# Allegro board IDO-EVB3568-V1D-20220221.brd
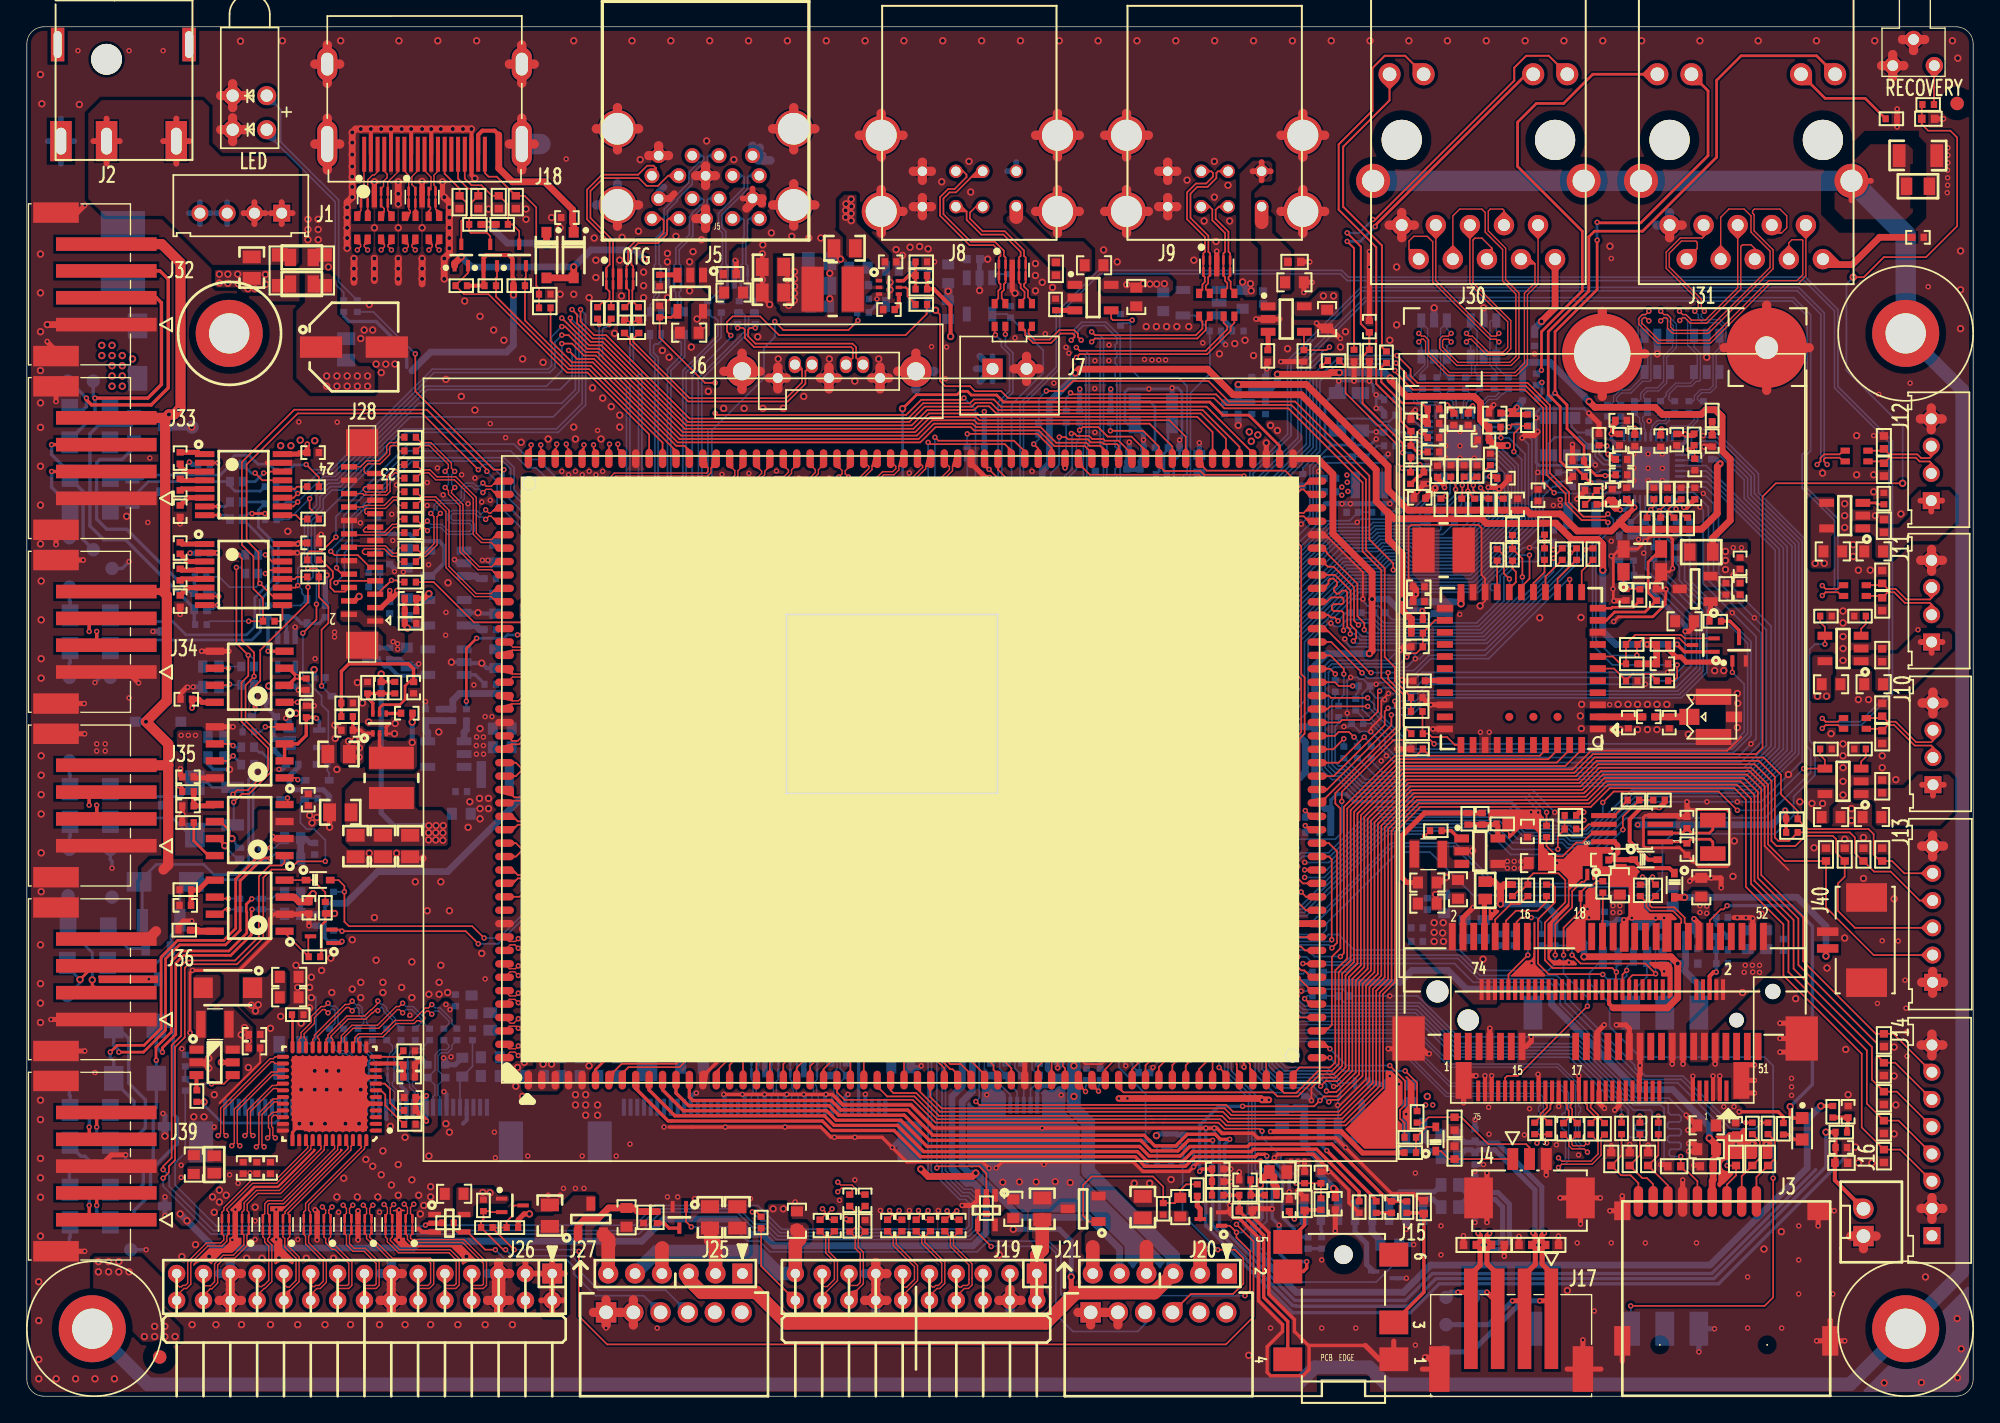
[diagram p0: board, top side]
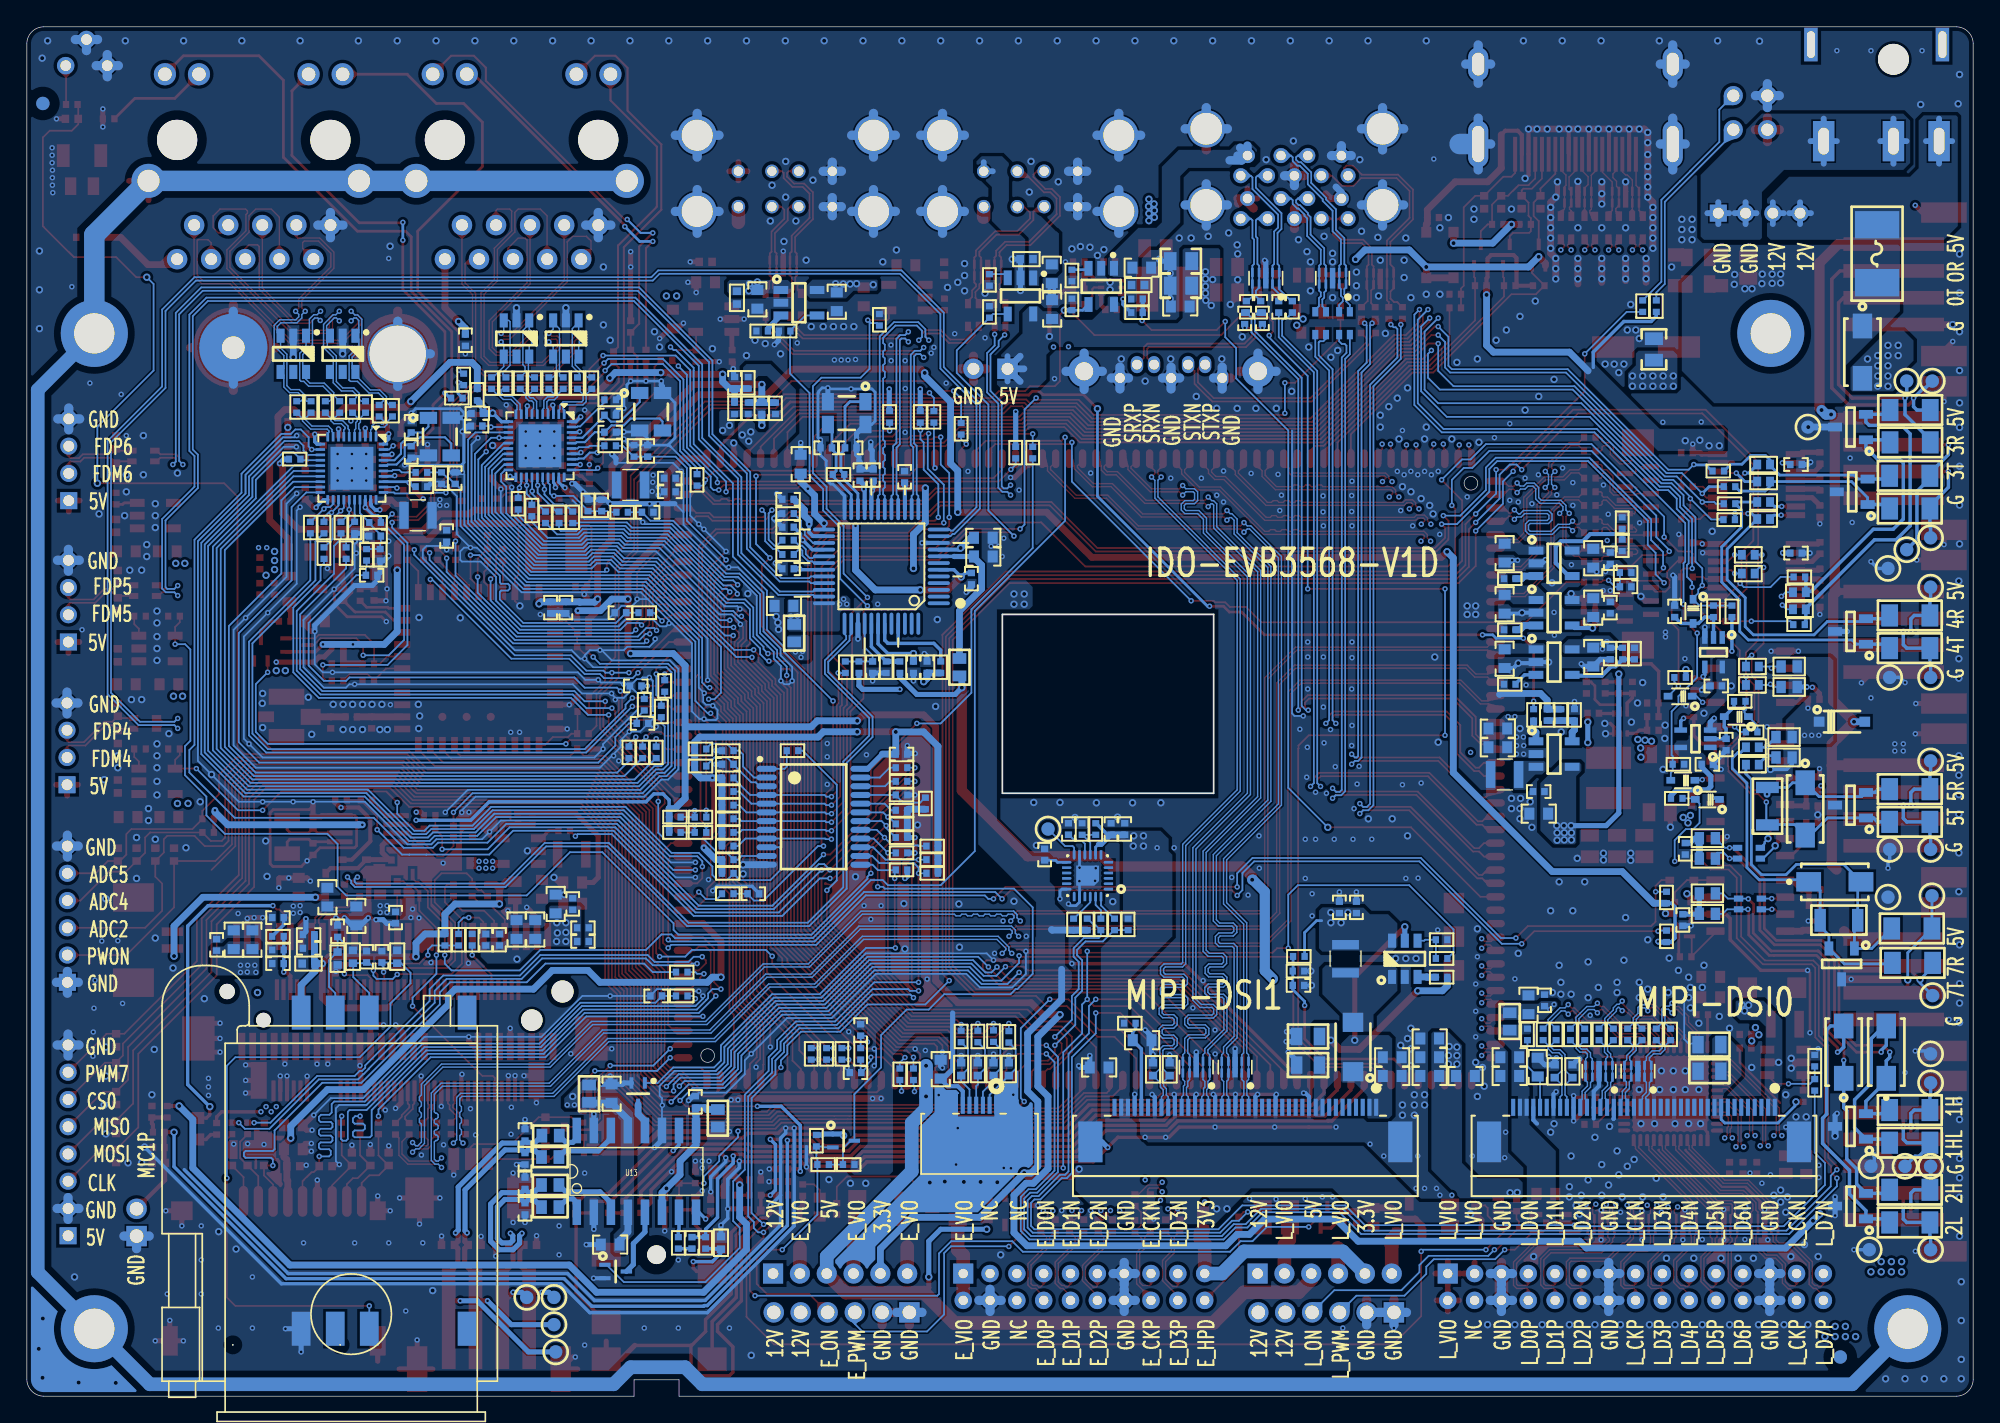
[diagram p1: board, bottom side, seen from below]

Outline 145.08 x 102.11 mm; copper layers: TOP, VCC, GND, BOTTOM. Coordinates in mm from the lower left corner of the outline.
Outline path: 0,100.84 arc(0.37,101.74) 1.27,102.11 143.81,102.11 arc(144.71,101.74) 145.08,100.84 145.08,1.27 arc(144.71,0.37) 143.81,0 99.82,0 99.82,1.22 96.47,1.22 96.47,0 1.27,0 arc(0.37,0.37) 0,1.27 0,100.84

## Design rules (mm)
net group DIFFPAIR0: nets HDMI_TX_D2N HDMI_TX_D2P
net group DIFFPAIR1: nets HDMI_TX_D2N_ HDMI_TX_D2P_
net group DIFFPAIR2: nets HDMI_TX_D1N_ HDMI_TX_D1P_
net group DIFFPAIR3: nets HDMI_TX_D1N HDMI_TX_D1P
net group DIFFPAIR4: nets HDMI_TX_D0N_ HDMI_TX_D0P_
net group DIFFPAIR5: nets HDMI_TX_D0N HDMI_TX_D0P
net group DIFFPAIR6: nets HDMI_TX_CLKN_ HDMI_TX_CLKP_
net group DIFFPAIR7: nets HDMI_TX_CLKN HDMI_TX_CLKP
net group DIFFPAIR8: nets USB2_HOST3_DM_ USB2_HOST3_DP_
net group DIFFPAIR9: nets FE2.1_DM1_ FE2.1_DP1_
net group DIFFPAIR10: nets FE2.1_DM1 FE2.1_DP1
net group DIFFPAIR11: nets USB2_HOST3_DM USB2_HOST3_DP
net group DIFFPAIR12: nets FE2.1_DM2_ FE2.1_DP2_
net group DIFFPAIR13: nets FE2.1_DM3_ FE2.1_DP3_
net group DIFFPAIR14: nets FE2.1_DM2 FE2.1_DP2
net group DIFFPAIR15: nets FE2.1_DM3 FE2.1_DP3
net group DIFFPAIR16: nets LVDS0_D0N LVDS0_D0P
net group DIFFPAIR17: nets LVDS0_D1N LVDS0_D1P
net group DIFFPAIR18: nets LVDS0_D2N LVDS0_D2P
net group DIFFPAIR19: nets LVDS0_CLKN LVDS0_CLKP
net group DIFFPAIR20: nets LVDS0_D3N LVDS0_D3P
net group DIFFPAIR21: nets LVDS1_D0N LVDS1_D0P
net group DIFFPAIR22: nets LVDS1_D1N LVDS1_D1P
net group DIFFPAIR23: nets LVDS1_D2N LVDS1_D2P
net group DIFFPAIR24: nets LVDS1_CLKN LVDS1_CLKP
net group DIFFPAIR25: nets LVDS1_D3N LVDS1_D3P
net group DIFFPAIR26: nets EDP_TX_D3N EDP_TX_D3P
net group DIFFPAIR27: nets EDP_TX_D3N_ EDP_TX_D3P_
net group DIFFPAIR28: nets EDP_TX_AUXN EDP_TX_AUXP
net group DIFFPAIR29: nets EDP_TX_AUXN_ EDP_TX_AUXP_
net group DIFFPAIR30: nets EDP_TX_D2N EDP_TX_D2P
net group DIFFPAIR31: nets EDP_TX_D2N_ EDP_TX_D2P_
net group DIFFPAIR32: nets EDP_TX_D1N EDP_TX_D1P
net group DIFFPAIR33: nets EDP_TX_D1N_ EDP_TX_D1P_
net group DIFFPAIR34: nets EDP_TX_D0N EDP_TX_D0P
net group DIFFPAIR35: nets EDP_TX_D0N_ EDP_TX_D0P_
net group DIFFPAIR36: nets USB3_HOST1_SSRXN_ USB3_HOST1_SSRXP_
net group DIFFPAIR37: nets USB3_HOST1_DM_ USB3_HOST1_DP_
net group DIFFPAIR38: nets USB3_OTG0_DM_ USB3_OTG0_DP_
net group DIFFPAIR39: nets USB3_OTG0_SSTXN_ USB3_OTG0_SSTXP_
net group DIFFPAIR40: nets USB3_HOST1_SSTXN_ USB3_HOST1_SSTXP_
net group DIFFPAIR41: nets USB3_HOST1_SSTXN USB3_HOST1_SSTXP
net group DIFFPAIR42: nets SATA1_TXN SATA1_TXP
net group DIFFPAIR43: nets USB3_OTG0_SSTXN USB3_OTG0_SSTXP
net group DIFFPAIR44: nets USB3_OTG0_DM USB3_OTG0_DP
net group DIFFPAIR45: nets USB3_HOST1_DM USB3_HOST1_DP
net group DIFFPAIR46: nets SATA1_RXN SATA1_RXP
net group DIFFPAIR47: nets USB3_HOST1_SSRXN USB3_HOST1_SSRXP
net group DIFFPAIR48: nets USB3_OTG0_SSRXN_ USB3_OTG0_SSRXP_
net group DIFFPAIR49: nets USB3_OTG0_SSRXN USB3_OTG0_SSRXP
net group DIFFPAIR50: nets FE2.1_DM5_ FE2.1_DP5_
net group DIFFPAIR51: nets FE2.1_DM5 FE2.1_DP5
net group DIFFPAIR52: nets FE2.1_DM6_ FE2.1_DP6_
net group DIFFPAIR53: nets FE2.1_DM6 FE2.1_DP6
net group DIFFPAIR54: nets FE2.1_DM4_ FE2.1_DP4_
net group DIFFPAIR55: nets FE2.1_DM4 FE2.1_DP4
net group DIFFPAIR56: nets MIPI_DSI_TX0_D3N_ MIPI_DSI_TX0_D3P_
net group DIFFPAIR57: nets MIPI_DSI_TX0_D2N_ MIPI_DSI_TX0_D2P_
net group DIFFPAIR58: nets MIPI_DSI_TX0_D3N MIPI_DSI_TX0_D3P
net group DIFFPAIR59: nets MIPI_DSI_TX0_D2N MIPI_DSI_TX0_D2P
net group DIFFPAIR60: nets MIPI_DSI_TX0_CLKN_ MIPI_DSI_TX0_CLKP_
net group DIFFPAIR61: nets MIPI_DSI_TX0_D1N_ MIPI_DSI_TX0_D1P_
net group DIFFPAIR62: nets MIPI_DSI_TX0_D1N MIPI_DSI_TX0_D1P
net group DIFFPAIR63: nets MIPI_DSI_TX0_CLKN MIPI_DSI_TX0_CLKP
net group DIFFPAIR64: nets MIPI_DSI_TX1_D3N MIPI_DSI_TX1_D3P
net group DIFFPAIR65: nets MIPI_DSI_TX1_D2N MIPI_DSI_TX1_D2P
net group DIFFPAIR66: nets MIPI_DSI_TX1_CLKN MIPI_DSI_TX1_CLKP
net group DIFFPAIR67: nets MIPI_DSI_TX1_D1N MIPI_DSI_TX1_D1P
net group DIFFPAIR68: nets MIPI_DSI_TX1_D0N MIPI_DSI_TX1_D0P
net group DIFFPAIR69: nets MIPI_DSI_TX0_D0N_ MIPI_DSI_TX0_D0P_
net group DIFFPAIR70: nets MIPI_DSI_TX0_D0N MIPI_DSI_TX0_D0P
net group DIFFPAIR71: nets USB2_HOST2_DM USB2_HOST2_DP
net group DIFFPAIR72: nets FE2.1_DM0 FE2.1_DP0
net group DIFFPAIR73: nets PCIE20_TXN PCIE20_TXP
net group DIFFPAIR74: nets PCIE20_RXN PCIE20_RXP
net group DIFFPAIR75: nets PCIE20_REFCLKN PCIE20_REFCLKP
net group DIFFPAIR76: nets PHY0_MDI3+ PHY0_MDI3-
net group DIFFPAIR77: nets PHY0_MDI2+ PHY0_MDI2-
net group DIFFPAIR78: nets PHY0_MDI1+ PHY0_MDI1-
net group DIFFPAIR79: nets LAN0_B+ LAN0_B-
net group DIFFPAIR80: nets LAN0_C+ LAN0_C-
net group DIFFPAIR81: nets LAN0_D+ LAN0_D-
net group DIFFPAIR82: nets LAN0_A+ LAN0_A-
net group DIFFPAIR83: nets PHY0_MDI0+ PHY0_MDI0-
net group DIFFPAIR84: nets PHY1_MDI0+ PHY1_MDI0-
net group DIFFPAIR85: nets LAN1_A+ LAN1_A-
net group DIFFPAIR86: nets LAN1_B+ LAN1_B-
net group DIFFPAIR87: nets PHY1_MDI1+ PHY1_MDI1-
net group DIFFPAIR88: nets LAN1_C+ LAN1_C-
net group DIFFPAIR89: nets PHY1_MDI2+ PHY1_MDI2-
net group DIFFPAIR90: nets PHY1_MDI3+ PHY1_MDI3-
net group DIFFPAIR91: nets LAN1_D+ LAN1_D-
net group DIFFPAIR92: nets FE2.1_DM7 FE2.1_DP7
net group DIFFPAIR93: nets FE2.1_DM7_ FE2.1_DP7_
net group DIFFPAIR96: nets REFCLKN_ REFCLKP_
net group DIFFPAIR97: nets VOLN VOLP
net group DIFFPAIR98: nets VORN VORP
net group DIFFPAIR99: nets MIPI_CSI_RX_D0N MIPI_CSI_RX_D0P
net group DIFFPAIR100: nets MIPI_CSI_RX_D1N MIPI_CSI_RX_D1P
net group DIFFPAIR101: nets MIPI_CSI_RX_D2N MIPI_CSI_RX_D2P
net group DIFFPAIR102: nets MIPI_CSI_RX_D3N MIPI_CSI_RX_D3P
net group DIFFPAIR103: nets MIPI_CSI_RX_CLK0N MIPI_CSI_RX_CLK0P
net group DIFFPAIR104: nets MIPI_CSI_D0N MIPI_CSI_D0P
net group DIFFPAIR105: nets MIPI_CSI_D1N MIPI_CSI_D1P
net group DIFFPAIR106: nets MIPI_CSI_D2N MIPI_CSI_D2P
net group DIFFPAIR107: nets MIPI_CSI_D3N MIPI_CSI_D3P
net group DIFFPAIR108: nets MIPI_CSI_CLKN MIPI_CSI_CLKP
net group DIFFPAIR109: nets PCIE20_RXN_ PCIE20_RXP_
net group DIFFPAIR110: nets PCIE20_TXN_ PCIE20_TXP_
net group PWR-20: nets VDD_RTC
net group SD-12: nets SD_CMD SD_D0 SD_D1 SD_D2 SD_D3

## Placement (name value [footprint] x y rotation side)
C2  100nF  [C0402L]  64.26 81.03 0 top
C3  10uF  [C0805L]  23.8 78.05 270 bottom
C4  100uF/25V  [CAPAE660X770]  24.38 78.23 0 top
C6  10uF  [C0805L]  60.96 85.6 0 top
C7  100nF  [C0402L]  64.39 84.58 180 top
C8  100pF  [C0402L]  66.67 83.57 0 top
C9  22uF  [C0805L]  59.05 82.8 180 bottom
C10  22uF  [C0805L]  55.63 84.2 0 top
C11  22uF  [C0805L]  55.63 82.3 0 top
C12  100nF  [C0402L]  28.83 52.83 90 top
C14  1nF  [C0402L]  50.29 30.63 0 bottom
C16  100nF  [C0402L]  28.32 50.93 180 top
C17  10uF  [C0603L]  32.38 43.43 180 bottom
C18  1uF  [C0402L]  32.38 45.09 180 bottom
C19  6.8pF  [C0402L]  31.75 50.8 90 bottom
C20  22uF  [C0603L]  35.43 48.39 0 bottom
C21  22uF  [C0603L]  35.43 49.78 0 bottom
C22  10uF  [C0805L]  23.24 47.88 0 top
C23  100nF  [C0402L]  23.88 49.66 0 top
C24  100pF  [C0402L]  26.42 52.83 90 top
C25  22uF  [C0805L]  26.54 41.02 90 top
C26  22uF  [C0805L]  24.51 41.02 90 top
C27  22uF  [C0805L]  28.57 41.02 90 top
C30  10uF  [C0603L]  40.51 26.67 180 bottom
C31  10uF  [C0603L]  40.51 23.88 180 bottom
C32  10uF  [C0603L]  37.85 23.88 0 bottom
C33  10uF  [C0603L]  40.51 25.27 180 bottom
C34  NC/6.8pF  [C0402L]  98.17 29.84 180 bottom
C35  10uF  [C0603L]  125.22 18.41 0 top
C36  100nF  [C0402L]  50.75 81.23 90 bottom
C37  100nF  [C0402L]  51.77 81.23 90 bottom
C38  10uF  [C0603L]  61.98 84.15 0 bottom
C40  NC/100nF  [C0402L]  53.11 81.23 90 bottom
C41  10uF  [C0603L]  59.11 81.25 180 bottom
C42  NC/100nF  [C0402L]  54.18 81.23 90 bottom
C43  10uF  [C0603L]  52.68 82.3 180 top
C45  10uF  [C0603L]  49.38 79.3 0 top
C46  10nF  [C0402L]  54.31 80.37 90 bottom
C47  10nF  [C0402L]  52.98 80.37 90 bottom
C48  22uF  [C0805L]  59.05 84.63 180 bottom
C50  10nF  [C0402L]  44.55 79.71 90 top
C51  10nF  [C0402L]  45.62 79.71 90 top
C52  10uF  [C0603L]  68.68 83.69 90 bottom
C53  10uF  [C0603L]  68.66 81.03 270 bottom
C54  10uF  [C0603L]  79.55 84.33 180 top
C55  10uF  [C0603L]  82.7 81.97 90 top
C56  10uF  [C0603L]  84.71 81.61 90 bottom
C57  10uF  [C0603L]  90.63 81.79 90 bottom
C58  10uF  [C0603L]  73.79 62.61 0 bottom
C59  10uF  [C0603L]  73.79 64.01 0 bottom
C60  NC/100nF  [C0402L]  82.04 54.36 90 bottom
C61  10uF  [C0603L]  94.49 83.06 180 top
C62  10uF  [C0603L]  96.93 80.31 90 top
C63  10uF  [C0603L]  87.4 69.49 270 bottom
C64  18pF  [C0402L]  83.67 70.71 0 bottom
C65  18pF  [C0402L]  85.5 70.71 180 bottom
C66  22uF  [C0603L]  88.65 58.93 180 bottom
C67  10uF  [C0603L]  137.54 43.18 0 top
C68  100nF  [C0402L]  77.98 54.36 270 bottom
C69  100nF  [C0402L]  88.34 61.7 180 bottom
C70  100nF  [C0402L]  78.99 54.36 90 bottom
C71  100nF  [C0402L]  79.65 68.55 270 bottom
C72  100nF  [C0402L]  88.34 66.88 180 bottom
C73  100nF  [C0402L]  81.99 68.68 270 bottom
C74  100nF  [C0402L]  88.34 64.8 180 bottom
C75  100nF  [C0402L]  74.68 60.96 90 bottom
C76  100nF  [C0402L]  82.98 68.68 270 bottom
C77  10uF  [C0603L]  134.49 43.18 180 top
C78  10uF  [C0603L]  137.67 62.99 0 top
C79  10uF  [C0603L]  134.62 62.99 180 top
C80  1uF  [C0402L]  90.81 16.13 0 top
C81  100nF  [C0402L]  88.77 16.94 180 top
C82  100nF  [C0402L]  96.47 16.31 270 top
C83  1uF  [C0402L]  135.76 21.21 270 top
C84  220pF  [C0402L]  135.25 18.54 180 top
C85  1uF  [C0402L]  94.11 14.22 270 top
C86  100nF  [C0402L]  95.5 11.43 90 bottom
C87  1nF  [C0402L]  107.95 15.88 90 bottom
C88  1nF  [C0402L]  107.95 13.97 270 bottom
C89  100nF  [C0402L]  101.73 14.1 90 top
C90  1nF  [C0402L]  107.95 17.7 270 bottom
C91  1nF  [C0402L]  107.95 19.48 90 bottom
C92  10uF  [C0603L]  101.5 22.56 270 bottom
C93  10uF  [C0603L]  101.6 11.3 180 bottom
C94  100nF  [C0402L]  97.54 14.35 90 top
C95  100nF  [C0402L]  95.25 21.95 270 bottom
C96  100nF  [C0402L]  40.26 87.88 0 top
C97  100nF  [C0402L]  59.13 12.73 90 top
C98  100nF  [C0402L]  60.2 12.73 90 top
C99  100nF  [C0402L]  61.34 14.61 90 top
C100  100nF  [C0402L]  62.48 14.61 90 top
C101  100nF  [C0402L]  64.16 12.73 90 top
C102  100nF  [C0402L]  65.23 12.73 90 top
C103  100nF  [C0402L]  66.29 12.73 90 top
C104  100nF  [C0402L]  67.36 12.73 90 top
C105  100nF  [C0402L]  68.43 12.73 90 top
C106  100nF  [C0402L]  69.49 12.73 90 top
C107  10uF  [C0603L]  57.4 13.08 270 top
C108  1uF  [C0603L]  73.53 13.97 270 top
C110  10uF  [C0805L]  83.19 14.1 270 top
C111  1uF  [C0603L]  85.98 14.1 270 top
C112  10uF  [C0805L]  75.69 13.97 270 top
C113  100nF  [C0402L]  16.97 25.96 180 top
C114  4.7uF  [C0402L]  16.97 26.97 180 top
C115  1uF  [C0603L]  19.56 29.74 180 top
C116  1uF  [C0603L]  19.56 31.27 180 top
C117  10uF  [C0603L]  34.54 23.88 180 bottom
C118  10uF  [C0603L]  32.46 24.54 270 bottom
C119  1uF  [C0603L]  43.31 23.88 0 bottom
C120  1uF  [C0603L]  43.31 25.27 0 bottom
C121  100nF  [C0402L]  45.97 36.45 270 bottom
C122  4.7uF  [C0402L]  47.24 36.45 270 bottom
C123  10uF  [C0603L]  65.15 24.51 180 bottom
C124  10uF  [C0603L]  76.96 24.38 270 bottom
C125  10uF  [C0603L]  61.95 26.54 0 bottom
C126  100nF  [C0402L]  28.5 23.8 180 top
C127  10uF  [C0603L]  33.15 29.18 270 bottom
C128  10uF  [C0603L]  34.54 25.27 180 bottom
C129  1uF  [C0402L]  28.5 24.69 180 top
C130  100nF  [C0402L]  31.95 29.51 270 bottom
C131  1uF  [C0402L]  28.55 22.28 180 top
C132  10uF  [C0603L]  12.45 17.27 270 top
C133  100nF  [C0402L]  16.13 17.02 90 top
C134  1uF  [C0402L]  18.16 17.02 90 top
C135  100nF  [C0402L]  17.14 17.02 90 top
C138  10uF  [C0805L]  50.93 13.34 270 top
C139  1uF  [C0603L]  31.85 15.09 0 top
C140  10uF  [C0805L]  52.96 13.34 270 top
C141  1uF  [C0603L]  44.7 13.34 270 top
C142  10uF  [C0805L]  38.99 13.46 270 top
C143  10uF  [C0603L]  34.92 62.87 90 bottom
C144  10uF  [C0603L]  28.32 62.48 90 bottom
C145  100nF  [C0402L]  27.05 62.48 90 bottom
C146  100nF  [C0402L]  25.91 60.35 0 bottom
C147  10uF  [C0603L]  34.92 59.05 90 bottom
C148  10uF  [C0603L]  28.32 58.8 90 bottom
C149  100nF  [C0402L]  27.05 58.8 90 bottom
C150  10uF  [C0603L]  34.92 54.99 90 bottom
C151  10uF  [C0603L]  28.32 55.12 90 bottom
C152  100nF  [C0402L]  27.05 55.37 90 bottom
C153  NC/6.8pF  [C0402L]  100.84 58.42 180 bottom
C154  10pF  [C0402L]  120.9 50.65 180 top
C155  18pF  [C0402L]  121.46 59.74 90 top
C156  NC/10pF  [C0402L]  119.38 50.22 90 top
C157  NC/10pF  [C0402L]  122.43 50.22 90 top
C158  18pF  [C0402L]  119.2 59.77 90 top
C161  1uF  [C0402L]  121.92 54.61 180 top
C162  1uF  [C0402L]  106.05 58.8 90 bottom
C163  100nF  [C0402L]  104.9 58.8 90 bottom
C164  100nF  [C0402L]  127.71 62.1 270 top
C165  1uF  [C0402L]  127.71 60.2 90 top
C166  10uF  [C0603L]  123.57 57.78 180 top
C167  4.7uF  [C0402L]  103.76 60.35 0 top
C168  NC/6.8pF  [C0402L]  103.63 55.88 0 top
C169  18pF  [C0402L]  101.6 71.88 0 bottom
C170  18pF  [C0402L]  101.6 73.15 0 bottom
C171  NC/6.8pF  [C0402L]  98.81 70.48 270 bottom
C172  NC/100pF  [C0402L]  103.17 72.39 270 top
C173  NC/100pF  [C0402L]  100.08 79.76 270 top
C174  NC/6.8pF  [C0402L]  82.93 27.3 270 bottom
C175  4.7uF  [C0402L]  110.03 68.45 180 top
C176  100nF  [C0402L]  97.16 68.45 0 bottom
C177  100nF  [C0402L]  97.16 67.44 0 bottom
C178  100nF  [C0402L]  107.44 72.85 90 top
C179  10nF  [C0402L]  112.39 78.74 90 bottom
C180  100nF  [C0402L]  106.38 72.85 90 top
C181  100nF  [C0402L]  104.85 71.48 180 top
C182  100nF  [C0402L]  111.56 72.34 180 bottom
C183  1uF  [C0402L]  92.33 75.56 270 bottom
C184  1uF  [C0402L]  105.16 68.96 270 top
C185  100nF  [C0402L]  108.58 71.3 0 top
C186  NC/6.8pF  [C0402L]  98.81 65.91 0 bottom
C187  4.7uF  [C0402L]  104.85 72.54 180 top
C188  100nF  [C0402L]  104.85 73.61 180 top
C189  100nF  [C0402L]  109.42 73.3 0 top
C190  4.7uF  [C0402L]  103.84 66.95 0 top
C191  100nF  [C0402L]  111.51 73.28 180 bottom
C192  18pF  [C0402L]  116.43 70.41 90 bottom
C193  18pF  [C0402L]  116.43 72.29 270 bottom
C194  NC/6.8pF  [C0402L]  113.16 68.45 270 bottom
C195  NC/100pF  [C0402L]  118.87 68.71 180 top
C196  NC/100pF  [C0402L]  115.67 68.58 0 top
C197  NC/6.8pF  [C0402L]  99.19 50.16 0 bottom
C199  4.7uF  [C0402L]  121.79 71.22 90 top
C200  100nF  [C0402L]  112.65 67.18 270 top
C201  100nF  [C0402L]  124.33 67.31 270 top
C202  10nF  [C0402L]  140.97 86.41 180 top
C203  100nF  [C0402L]  113.79 64.14 90 bottom
C204  100nF  [C0402L]  118.87 69.85 180 top
C205  100nF  [C0402L]  119.86 71.27 90 top
C206  1nF  [C1206L]  140.97 92.51 180 top
C207  100nF  [C0402L]  124.33 69.47 90 top
C208  1uF  [C0402L]  119.25 67.31 270 top
C209  1uF  [C0402L]  90.3 73.66 90 bottom
C210  100nF  [C0402L]  111.12 66.5 270 top
C211  NC/6.8pF  [C0402L]  119.38 61.21 0 bottom
C212  4.7uF  [C0402L]  118.19 67.21 270 top
C213  100nF  [C0402L]  125.63 71.22 90 top
C214  100nF  [C0402L]  118.85 72.77 180 top
C215  4.7uF  [C0402L]  118.72 71.32 90 top
C216  100nF  [C0402L]  122.99 71.32 90 top
C217  100nF  [C0402L]  21.34 70.36 180 top
C218  100nF  [C0402L]  11.43 69.95 90 top
C219  100nF  [C0402L]  11.43 67.97 90 top
C220  100nF  [C0402L]  13.21 69.47 0 bottom
C221  100nF  [C0402L]  11.43 65.99 90 top
C222  100nF  [C0402L]  21.34 63.63 180 top
C223  100nF  [C0402L]  11.43 63.25 90 top
C224  100nF  [C0402L]  11.43 61.26 90 top
C225  100nF  [C0402L]  13.21 62.87 0 bottom
C226  100nF  [C0402L]  11.43 59.28 90 top
C227  1nF  [C0402L]  22.25 58.52 270 bottom
C228  1uF  [C0402L]  11.89 51.97 0 top
C229  100nF  [C0402L]  19.15 52.96 180 bottom
C230  1nF  [C0402L]  18.41 48.59 90 bottom
C231  100nF  [C0402L]  19.81 47.12 0 bottom
C232  1uF  [C0402L]  12.01 46.18 0 top
C233  1uF  [C0402L]  20.98 44.48 270 top
C234  1uF  [C0402L]  12.01 44.02 0 top
C235  100nF  [C0402L]  21.46 40.82 90 bottom
C236  1uF  [C0402L]  21.03 36.42 90 top
C237  1uF  [C0402L]  11.81 36.6 0 top
C238  100nF  [C0402L]  21.64 35.51 90 bottom
C239  18pF  [C0402L]  123.75 40.79 270 top
C240  18pF  [C0402L]  123.75 42.77 90 top
C241  1uF  [C0402L]  117.47 39.98 0 top
C242  100nF  [C0402L]  63.25 42.29 270 bottom
C243  1uF  [C0402L]  69.22 40.39 270 bottom
C244  1uF  [C0402L]  64.26 42.29 270 bottom
C245  100nF  [C0402L]  67.44 42.29 270 bottom
C246  22uF  [C0603L]  104.39 38.3 180 top
C247  22uF  [C0603L]  104.39 36.73 180 top
C248  33pF  [C0402L]  110.87 34.04 270 bottom
C249  100nF  [C0402L]  114.55 19.94 270 top
C251  100nF  [C0402L]  115.57 19.94 270 top
C252  100nF  [C0402L]  126.36 32.26 180 bottom
C253  22uF  [C0603L]  124.82 37.95 270 top
C254  100nF  [C0402L]  130.94 33.66 270 bottom
C255  22uF  [C0603L]  129.67 34.04 270 bottom
C256  22uF  [C0603L]  107.19 34.8 270 bottom
C257  22uF  [C0603L]  108.58 34.8 270 bottom
C258  22uF  [C0603L]  118.75 38.1 270 top
C259  33pF  [C0402L]  127.38 19.94 90 top
C260  100nF  [C0402L]  124.08 34.42 180 bottom
C261  100pF  [C0402L]  124.08 33.4 180 bottom
C262  33pF  [C0402L]  118.62 32.77 270 bottom
C263  10uF  [C0603L]  112.65 39.75 180 top
C264  1uF  [C0402L]  111.86 42.11 270 top
C265  6.8pF  [C0402L]  108.48 43.05 90 top
C266  22uF  [C0603L]  125.22 20.19 0 top
C267  22uF  [C0603L]  106.68 37.8 270 top
C268  1uF  [C0402L]  79.88 47.88 0 bottom
C269  1uF  [C0402L]  92.84 47.12 180 bottom
C270  NC/6.8pF  [C0402L]  90.93 37.47 0 bottom
C271  33pF  [C0402L]  119.76 32.77 270 bottom
C272  33pF  [C0402L]  121.92 34.67 270 bottom
C273  33pF  [C0402L]  104.39 36.7 270 bottom
C274  22uF  [C0603L]  120.52 35.81 90 bottom
C275  22uF  [C0603L]  128.27 34.04 270 bottom
C276  22uF  [C0603L]  105.66 36.7 270 bottom
C277  22uF  [C0603L]  122.68 37.21 270 bottom
C278  100nF  [C0402L]  109.86 34.04 270 bottom
C482  10pF  [C0402L]  103.63 34.92 0 bottom
C483  33pF  [C0402L]  126.36 35.69 180 bottom
C484  100nF  [C0402L]  103.63 33.91 0 bottom
C485  10pF  [C0402L]  117.6 35.69 90 bottom
C486  22uF  [C0805L]  23.37 43.54 0 top
C488  10uF  [C0805L]  16.76 84.15 270 top
C489  10uF  [C0603L]  137.67 53.09 0 top
C490  10uF  [C0603L]  134.49 53.09 180 top
C491  100nF  [C0402L]  103.76 59.26 0 top
C492  NC/18pF  [C0402L]  28.6 59.49 180 top
C493  NC/6.8pF  [C0402L]  83.31 24.13 180 bottom
C494  NC/6.8pF  [C0402L]  99.69 52.96 180 bottom
C496  NC/6.8pF  [C0402L]  102.23 66.42 270 bottom
C497  NC/6.8pF  [C0402L]  119.13 64.14 180 bottom
D1  SMAJ15A  [SMA_DO-214AC]  8.26 77.85 270 bottom
D2  ES0402V014CT  [V0402]  125.22 17.14 180 top
D3  ES0402V014CT  [V0402]  120.85 17.68 90 top
D4  ES0402V014CT  [V0402]  119.48 17.68 90 top
D5  ES0402V014CT  [V0402]  129.79 17.68 90 top
D6  ES0402V014CT  [V0402]  128.63 17.68 90 top
D7  ES0402V014CT  [V0402]  127.41 17.68 90 top
D8  ES0402V014CT  [V0402]  118.11 17.68 90 top
D9  ES0402V014CT  [V0402]  122.81 17.14 180 top
D10  LRB520S-30T1G  [SOD523]  105.03 19.18 90 top
D11  ES0402V014CT  [V0402]  106.43 18.16 90 top
D12  ES0402V014CT  [V0402]  106.43 20.32 270 top
D13  ES0402V014CT  [V0402]  62.26 82.85 180 bottom
D14  ES0402V014CT  [V0402]  52.4 83.67 0 top
D15  MKT642U05  [ESD-DFN2510A-10]  47.75 83.36 0 bottom
D16  MKT642U05  [ESD-DFN2510A-10]  52.73 83.36 0 bottom
D17  MKT642U05  [ESD-DFN2510A-10]  44.2 83.31 0 top
D18  MKT642U05  [ESD-DFN2510A-10]  73.46 83.97 0 top
D19  ES0402V014CT  [V0402]  70.56 84.79 0 bottom
D20  ES0402V014CT  [V0402]  76.71 84.07 270 top
D21  MKT642U05  [ESD-DFN2510A-10]  88.7 84.28 0 top
D22  ES0402V014CT  [V0402]  92.15 81.92 270 bottom
D23  ES0402V014CT  [V0402]  94.49 84.58 0 top
D24  ES0402V014CT  [V0402]  138.3 45.47 90 top
D25  ES0402V014CT  [V0402]  138.3 49.15 270 top
D26  ES0402V014CT  [V0402]  138.3 51.18 90 top
D27  ES0402V014CT  [V0402]  138.3 55.24 90 top
D28  ES0402V014CT  [V0402]  138.3 59.05 270 top
D29  ES0402V014CT  [V0402]  138.3 61.09 90 top
D30  ES0402V014CT  [V0402]  138.43 64.9 90 top
D31  ES0402V014CT  [V0402]  138.43 69.09 270 top
D32  ES0402V014CT  [V0402]  138.43 71.12 90 top
D33  ES0402V014CT  [V0402]  141.73 95.25 0 top
D34  ES0402V014CT  [V0402]  134.11 40.39 90 top
D35  ES0402V014CT  [V0402]  135.51 40.39 90 top
D36  ES0402V014CT  [V0402]  136.91 40.39 90 top
D37  ES0402V014CT  [V0402]  138.3 40.39 90 top
D38  ES0402V014CT  [V0402]  104.14 14.1 90 top
D39  ES0402V014CT  [V0402]  95.25 14.33 90 top
D40  ES0402V014CT  [V0402]  93.34 11.43 90 bottom
D41  ES0402V014CT  [V0402]  90.86 13.84 0 top
D42  ES0402V014CT  [V0402]  135.25 17.4 0 top
D43  ES0402V014CT  [V0402]  113.69 11.28 0 top
D44  ES0402V014CT  [V0402]  111.71 11.28 180 top
D45  ES0402V014CT  [V0402]  109.65 11.28 0 top
D46  ES0402V014CT  [V0402]  107.57 11.28 180 top
D47  MKT642U05  [ESD-DFN2510A-10]  25.91 89.41 0 top
D48  MKT642U05  [ESD-DFN2510A-10]  29.46 89.41 0 top
D49  B5819W-G  [SOD123]  38.73 85.09 270 top
D51  B5819W-G  [SOD123]  40.77 85.09 270 top
D52  MKT642U05  [ESD-DFN2510A-10]  24.99 24.23 0 bottom
D53  MKT642U05  [ESD-DFN2510A-10]  27.89 24.23 0 bottom
D54  ES0402V014CT  [V0402]  29.87 24.23 270 bottom
D55  ES0402V014CT  [V0402]  31.19 24.23 270 bottom
D56  SM340AF  [SMAF]  14.99 30.45 0 top
D57  MKT642U05  [ESD-DFN2510A-10]  55.02 24.54 0 bottom
D58  MKT642U05  [ESD-DFN2510A-10]  57.91 24.54 0 bottom
D59  ES0402V014CT  [V0402]  59.89 24.38 270 bottom
D60  SM340AF  [SMAF]  46.23 26.04 270 bottom
D61  ES0402V014CT  [V0402]  61.14 24.38 270 bottom
D62  ES0402V014CT  [V0402]  71.88 24.38 90 bottom
D63  ES0402V014CT  [V0402]  73.03 24.38 90 bottom
D64  ES0402V014CT  [V0402]  74.19 24.38 90 bottom
D65  ES0402V014CT  [V0402]  75.44 24.38 90 bottom
D66  MKT642U05  [ESD-DFN2510A-10]  27.74 12.8 180 top
D67  MKT642U05  [ESD-DFN2510A-10]  18.59 12.8 180 top
D68  MKT642U05  [ESD-DFN2510A-10]  24.69 12.8 180 top
D69  MKT642U05  [ESD-DFN2510A-10]  21.64 12.8 180 top
D70  MKT642U05  [ESD-DFN2510A-10]  15.54 12.8 180 top
D71  SRV05-4  [SOT23-6]  108.58 78.87 270 bottom
D72  SRV05-4  [SOT23-6]  104.9 78.87 270 bottom
D73  SRV05-4  [SOT23-6]  125.22 77.72 270 bottom
D74  SRV05-4  [SOT23-6]  121.54 77.72 270 bottom
D75  SMAJ12CA  [SMA_DO-214AC]  12.52 43.79 270 bottom
D78  PESD1CAN  [SOT23]  9.02 67.44 0 bottom
D81  PESD1CAN  [SOT23]  9.14 57.02 0 bottom
D82  LRB520S-30T1G  [SOD523]  21.84 52.2 0 bottom
D83  B5819W-G  [SOD123]  9.78 50.29 180 bottom
D84  LRB520S-30T1G  [SOD523]  20.88 58.52 270 bottom
D85  PESD1CAN  [SOT23]  9.14 44.07 0 bottom
D86  LRB520S-30T1G  [SOD523]  21.64 45.92 0 bottom
D87  PESD1CAN  [SOT23]  9.8 32.23 270 bottom
D88  LRB520S-30T1G  [SOD523]  17.65 50.67 0 bottom
D89  PESD1CAN  [SOT23]  9.14 20.12 0 bottom
D90  LRB520S-30T1G  [SOD523]  19.81 44.5 0 bottom
D91  PESD1CAN  [SOT23]  9.14 14.17 0 bottom
D92  LRB520S-30T1G  [SOD523]  120.68 40.01 0 top
D93  LRB520S-30T1G  [SOD523]  122.81 38.1 270 top
D94  ES0402V014CT  [V0402]  121.92 32.64 270 bottom
D95  ES0402V014CT  [V0402]  120.78 32.77 90 bottom
D96  ES0402V014CT  [V0402]  117.47 32.77 90 bottom
D97  ES0402V014CT  [V0402]  124.08 32.26 0 bottom
D98  ES0402V014CT  [V0402]  138.43 17.91 270 top
D99  ES0402V014CT  [V0402]  138.43 20.07 270 top
D100  ES0402V014CT  [V0402]  138.43 22.23 270 top
D101  ES0402V014CT  [V0402]  138.43 24.38 270 top
D102  ES0402V014CT  [V0402]  138.43 26.54 270 top
D103  PESD1CAN  [SOT23]  9.14 72.26 0 bottom
D104  SMAJ12CA  [SMA_DO-214AC]  10.31 38.35 180 bottom
D105  SMAJ12CA  [SMA_DO-214AC]  6.48 25.65 90 bottom
D106  SMAJ12CA  [SMA_DO-214AC]  9.65 25.65 90 bottom
D107  LRB520S-30T1G  [SOD523]  21.72 38.48 0 top
D108  ES0402V014CT  [V0402]  32.26 89.03 90 top
D109  ES0402V014CT  [V0402]  33.66 89.03 90 top
D110  ES0402V014CT  [V0402]  35.18 89.03 90 top
D111  ES0402V014CT  [V0402]  36.45 89.03 90 top
F1  FUSE_16V/3A  [SMD1812]  7.16 85.19 270 bottom
F2  FUSE_60V/0.1A  [SMD1206]  4.72 68.63 180 bottom
F3  FUSE_60V/0.1A  [SMD1206]  4.72 66.19 180 bottom
F4  FUSE_60V/0.1A  [SMD1206]  4.72 58.22 180 bottom
F5  FUSE_60V/0.1A  [SMD1206]  4.72 55.78 180 bottom
F6  FUSE_60V/0.1A  [SMD1206]  4.72 45.26 180 bottom
F7  FUSE_60V/0.1A  [SMD1206]  4.72 42.82 180 bottom
F8  FUSE_60V/0.1A  [SMD1206]  4.52 32.31 180 bottom
F9  FUSE_60V/0.1A  [SMD1206]  4.57 34.87 180 bottom
F10  FUSE_60V/0.1A  [SMD1206]  4.72 18.9 180 bottom
F11  FUSE_60V/0.1A  [SMD1206]  4.72 21.34 180 bottom
F12  FUSE_60V/0.1A  [SMD1206]  4.72 12.95 180 bottom
F13  FUSE_60V/0.1A  [SMD1206]  4.72 15.39 180 bottom
F14  FUSE_60V/0.1A  [SMD1206]  4.7 73.53 180 bottom
F15  FUSE_60V/0.1A  [SMD1206]  4.7 71.12 180 bottom
H1  HOLE  [MTG300_500]  140.06 5.03 0 top
H2  HOLE  [MTG300_500]  4.88 5.03 0 top
H3  HOLE  [MTG300_500]  15.09 79.25 0 top
H4  HOLE  [MTG300_500]  140.06 79.25 0 top
H5  HOLE  [MTG250_600]  129.69 78.18 0 top
J1  PH2.0-4A  [PH200-4A]  12.9 88.21 0 top
J2  -  [DC-044A-2_5]  5.94 103.78 270 top
J3  SD  [TF-01A]  128.93 14.33 0 top
J4  MX1.25T-S-3A  [MX125T-S-3A]  112.01 14.78 0 top
J5  USB-4AFx2  [USB3D0_AF_18P]  50.6 92.51 180 top
J6  -  [SATA30_7P_V_DIP]  63.6 75.92 0 top
J7  XH2.5-2A  [XH250-2A]  74.52 75.59 180 top
J8  USB-4AFx2  [DURAL_USB_AF_2X]  70.26 92.02 180 top
J9  USB-4AFx2  [DURAL_USB_AF_2X]  88.54 92.02 180 top
J10  PH2.0-4A  [PH200-4A]  142.09 51.69 270 top
J11  PH2.0-4A  [PH200-4A]  141.99 62.33 270 top
J12  PH2.0-4A  [PH200-4A]  141.96 72.87 270 top
J13  PH2.0-6A  [PH200-6A]  142.06 36.96 270 top
J14  PH2.0-8A  [PH200-8A]  142.01 18.06 270 top
J15  PJ-316-6A  [PJ-316A-6A]  98.15 0 270 top
J16  PH2.0-2A  [PH200-2A]  136.91 16 270 top
J17  PH2.0-S-4AW  [PH200-S-4AWZ]  110.64 7.77 180 top
J18  HDMI-19S  [HDMIA19_HDMI_01A-NEW]  25.15 92.61 0 top
J19  -  [HDR200MRA-2X10]  75.29 9.14 180 top
J20  -  [HDR200MA-1X6]  89.46 9.14 180 top
J21  PH2.0-6AW  [PH200-6AW]  83.36 6.25 180 top
J22  -  [FPC05-FDW-40P]  24.54 19.96 180 bottom
J23  -  [FPC05-FDW-40P]  54.25 19.96 180 bottom
J24  -  [FPC05-FDW-6P]  74.07 20.12 180 bottom
J25  -  [HDR200MA-1X6]  53.34 9.14 180 top
J26  -  [HDR200MRA-2X15]  39.17 9.14 180 top
J27  PH2.0-6AW  [PH200-6AW]  47.24 6.25 180 top
J28  FPC05-FDW-24P  [FPC05-ZDW-24P]  24.99 63.55 180 top
J29  IPEX  [IPEX-20279-001E]  125.73 50.65 180 top
J30  -  [HR911130X]  108.2 96.72 0 top
J31  -  [HR911130X]  128.17 96.72 0 top
J32  PH2.0-S-4AW  [PH200-S-4AWZ]  7.92 82.91 90 top
J33  PH2.0-S-4AW  [PH200-S-4AWZ]  7.92 69.95 90 top
J34  PH2.0-S-4AW  [PH200-S-4AWZ]  7.92 57 90 top
J35  PH2.0-S-4AW  [PH200-S-4AWZ]  7.92 44.04 90 top
J36  PH2.0-S-4AW  [PH200-S-4AWZ]  7.92 31.09 90 top
J39  PH2.0-S-5AW  [PH200-S-5AWZ]  7.92 16.15 90 top
J40  MX1.25T-S-2A  [MX125T-S-2A]  134.24 34.01 270 top
J41  MINI-PCIE-S52-H80  [M_MINIPCIE_SOCKET_CK]  117.65 30.18 180 top
L1  2.2uH/4.3A  [L4040]  60.07 82.55 180 top
L2  1uH/3.5A  [L2520]  34.92 46.35 0 bottom
L3  2.2uH/4.3A  [L4040]  27.18 46.1 270 top
L5  WCM2012F2SF-900T04  [CMLS-ACM2012]  46.86 80.01 90 bottom
L6  WCM2012F2SF-900T04  [CMLS-ACM2012]  48.64 80.01 90 bottom
L7  WCM2012F2SF-900T04  [CMLS-ACM2012]  72.54 80.62 90 top
L8  WCM2012F2SF-900T04  [CMLS-ACM2012]  74.52 80.62 90 top
L9  WCM2012F2SF-900T04  [CMLS-ACM2012]  87.78 81.38 90 top
L10  WCM2012F2SF-900T04  [CMLS-ACM2012]  89.61 81.38 90 top
L11  UPZ1608E101-3R0TF  [L0603]  87.88 56.9 90 bottom
L12  WCM2012F2SF-900T04  [CMLS-ACM2012]  136.27 50.16 0 top
L13  NC/UPZ1608E101-3R0TF  [L0603]  75.56 54.36 90 bottom
L14  WCM2012F2SF-900T04  [CMLS-ACM2012]  136.27 60.07 0 top
L15  WCM2012F2SF-900T04  [CMLS-ACM2012]  136.4 70.1 0 top
L16  UPZ1608E101-3R0TF  [L0603]  93.27 16.71 180 top
L17  UPZ1608E101-3R0TF  [L0603]  106.07 15.75 0 bottom
L18  UPZ1608E101-3R0TF  [L0603]  106.07 14.1 0 bottom
L19  UPZ1608E101-3R0TF  [L0603]  106.07 17.83 0 bottom
L20  UPZ1608E101-3R0TF  [L0603]  106.05 19.43 0 bottom
L21  UPZ1608E101-3R0TF  [L0603]  103.17 22.56 270 bottom
L22  UPZ1608E101-3R0TF  [L0603]  93.57 20.73 90 bottom
L23  WCM2012F2SF-900T04  [CMLS-ACM2012]  25.02 87.12 90 top
L24  WCM2012F2SF-900T04  [CMLS-ACM2012]  26.8 87.12 90 top
L25  WCM2012F2SF-900T04  [CMLS-ACM2012]  28.57 87.12 90 top
L26  WCM2012F2SF-900T04  [CMLS-ACM2012]  30.35 87.12 90 top
L27  4.7uH/1.4A  [L2520]  14.02 27.74 180 top
L28  4.7uH/1.4A  [L2520]  46.79 32.61 270 bottom
L29  UPZ1608E101-3R0TF  [L0603]  34.54 27.94 270 bottom
L30  UPZ1608E101-3R0TF  [L0603]  13.97 17.27 270 top
L31  4.7uH/2.85A  [L4040]  105.61 63.09 180 top
L32  2.2uH/2.1A  [L2520]  100.08 67.94 180 bottom
L33  2.2uH/2.1A  [L2520]  115.93 65.68 180 bottom
L34  GZ1005D121TF  [L0402]  15.62 68.2 180 bottom
L35  GZ1005D121TF  [L0402]  15.62 69.47 180 bottom
L36  GZ1005D121TF  [L0402]  15.62 66.67 0 bottom
L37  GZ1005D121TF  [L0402]  15.62 65.41 0 bottom
L38  NC/GZ1005D121TF  [L0402]  16.76 62.74 180 bottom
L39  NC/GZ1005D121TF  [L0402]  16.76 61.34 180 bottom
L40  NC/GZ1005D121TF  [L0402]  12.95 59.94 180 bottom
L41  NC/GZ1005D121TF  [L0402]  12.95 58.67 180 bottom
L42  GZ1005D121TF  [L0402]  16.46 53.04 0 bottom
L43  GZ1005D121TF  [L0402]  16.46 54.41 0 bottom
L44  GZ1005D121TF  [L0402]  16.46 47.09 0 bottom
L45  GZ1005D121TF  [L0402]  16.46 48.39 0 bottom
L46  WCM2012F2SF-900T04  [CMLS-ACM2012]  16.71 40.49 0 bottom
L47  WCM2012F2SF-900T04  [CMLS-ACM2012]  16.64 36.7 0 bottom
L48  UPZ1608E101-3R0TF  [L0603]  108.71 37.72 90 top
L49  1uH/3.5A  [L2520]  104.47 40.41 180 top
L50  NC/ACM453228R231  [CMLP-ACM4532]  20.51 83.95 0 top
LED1  LEDx2(R+G)  [LED_P254_2X2DIP]  16.61 95.71 180 top
LED2  RED LED0603  [LED0603]  132.33 19.94 270 top
M1  -  [MARK]  143.89 96.39 0 top
M2  -  [MARK]  9.91 2.92 0 top
M3  -  [MARK]  143.89 96.39 180 bottom
M4  -  [MARK]  9.91 2.92 180 bottom
M5  IDO-SOM3568  [SOM3568-204P]  34.9 22.86 0 top
Q1  DTC143ZE  [SOT523]  99.52 22.56 270 bottom
Q2  DTC143ZE  [SOT523]  101.19 9.3 180 bottom
Q3  MMFTN3019E  [SOT523]  34.54 85.09 90 top
Q4  MMFTN3019E  [SOT523]  36.7 85.09 90 top
Q5  MMFTN3019E  [SOT523]  32.38 85.09 90 top
Q6  CJ3401  [SOT23]  78.74 13.97 180 top
Q7  DTC143ZE  [SOT523]  88.27 13.21 180 top
Q8  NC/MMFTN3019E  [SOT523]  36.2 14.22 0 top
Q9  CJ3401  [SOT23]  42.04 13.21 90 top
Q10  DTC143ZE  [SOT523]  48.64 13.34 270 top
Q11  MMFTN3019E  [SOT523]  124.97 56.01 180 top
Q12  CJ3401  [SOT23]  124.36 60.2 180 top
Q13  DTC143ZE  [SOT523]  127.64 55.63 90 top
Q15  MMFTN3019E  [SOT523]  21.95 34.29 180 top
Q16  DTC143ZE  [SOT523]  115.82 38.1 270 top
Q17  NC/MMFTN3019E  [SOT523]  84.2 19.05 180 bottom
R3  100K  [R0402L]  23.88 50.67 180 top
R4  118K  [R0402L]  66.67 82.55 180 top
R5  47K  [R0402L]  23.88 51.69 0 top
R6  22K  [R0402L]  66.67 84.58 0 top
R7  47K  [R0402L]  50.27 32.79 0 bottom
R8  1K  [R0402L]  24.64 81.28 90 bottom
R9  1K  [R0402L]  23.62 81.28 90 bottom
R10  15K  [R0402L]  50.29 31.7 180 bottom
R12  200K  [R0402L]  30.73 50.8 270 bottom
R13  118K  [R0402L]  27.43 52.83 270 top
R14  10K  [R0402L]  32.77 50.8 270 bottom
R15  44.2K  [R0402L]  29.72 50.8 90 bottom
R16  10K  [R0402L]  66.67 81.41 180 top
R17  22K  [R0402L]  25.4 52.83 90 top
R18  22R  [R0402L]  129.79 19.96 270 top
R19  22R  [R0402L]  128.63 19.96 270 top
R20  22R  [R0402L]  96.27 31.62 0 bottom
R21  22R  [R0402L]  96.27 29.84 0 bottom
R22  22R  [R0402L]  121.62 19.96 270 top
R23  22R  [R0402L]  120.24 19.96 270 top
R24  22R  [R0402L]  118.87 19.96 270 top
R25  4.7K  [R0402L]  103.12 18.16 0 top
R26  100R  [R0402L]  103.12 19.3 0 top
R27  100R  [R0402L]  103.63 20.83 270 top
R28  10K  [R0402L]  62.33 81.81 0 bottom
R29  15K  [R0402L]  62.33 80.8 0 bottom
R30  0R  [R0402L]  42.55 80.77 90 top
R31  0R  [R0402L]  43.56 80.77 90 top
R32  NC/0R  [R0402L]  44.58 80.77 90 top
R33  NC/0R  [R0402L]  45.59 80.77 90 top
R34  510K  [R0402L]  67.18 81.41 90 bottom
R35  4.7K  [R0402L]  67.18 83.57 270 bottom
R36  510K  [R0402L]  47.17 80.87 90 top
R37  4.7K  [R0402L]  47.17 83.19 270 top
R39  22R  [R0402L]  84.07 54.36 90 bottom
R40  510K  [R0402L]  73.33 80.85 90 bottom
R41  6.8K  [R0402L]  73.33 83.24 270 bottom
R42  510K  [R0402L]  81.53 80.26 90 bottom
R43  6.8K  [R0402L]  76.68 81.41 90 top
R44  47K  [R0402L]  80.01 54.36 270 bottom
R45  100K  [R0402L]  81.03 54.36 270 bottom
R46  10K  [R0402L]  76.96 54.36 270 bottom
R47  510K  [R0402L]  88.6 79.43 0 bottom
R48  NC/100K  [R0402L]  83.06 54.36 90 bottom
R49  6.8K  [R0402L]  90.27 79.43 0 bottom
R50  0R  [R0402L]  88.34 62.76 0 bottom
R51  0R  [R0402L]  88.34 63.83 0 bottom
R52  510K  [R0402L]  95.2 77.57 270 top
R53  6.8K  [R0402L]  92.51 77.57 270 top
R54  2.7K  [R0402L]  88.34 65.81 0 bottom
R55  1M  [R0402L]  84.58 68.73 0 bottom
R56  510K  [R0402L]  134.11 48.26 0 top
R57  6.8K  [R0402L]  136.65 48.26 180 top
R59  6.8K  [R0402L]  138.43 66.93 90 top
R60  10K  [R0402L]  131.57 42.04 0 top
R61  10K  [R0402L]  131.57 43.05 0 top
R62  100R  [R0402L]  141.73 96.32 0 top
R68  2.2K  [R0402L]  90.81 14.99 0 top
R69  100R  [R0402L]  92.71 14.99 0 top
R70  100K  [R0402L]  88.77 14.99 180 top
R71  100K  [R0402L]  88.77 16 0 top
R72  100K  [R0402L]  95.25 16.31 270 top
R73  0R  [R0402L]  94.49 11.43 270 bottom
R74  1K  [R0402L]  96.47 14.33 270 top
R75  100R  [R0402L]  134.62 21.21 270 top
R76  0R  [R0402L]  102.87 14.1 270 top
R77  0R  [R0402L]  99.31 14.1 270 top
R78  2.2K  [R0402L]  135.25 19.68 180 top
R79  4.7K  [R0402L]  96.52 11.43 90 bottom
R80  4.7K  [R0402L]  100.58 14.1 90 top
R81  10K  [R0402L]  34.54 82.8 0 top
R82  1.8K  [R0402L]  33.4 87.38 180 top
R83  10K  [R0402L]  36.7 82.8 0 top
R84  1.8K  [R0402L]  35.43 87.38 0 top
R85  1K  [R0402L]  38.61 81.15 180 top
R86  100K  [R0402L]  38.61 82.17 0 top
R87  27K  [R0402L]  32.38 82.8 180 top
R88  22R  [R0402L]  54.74 12.95 270 top
R89  0R  [R0402L]  71.53 14.02 270 top
R90  100K  [R0402L]  84.71 13.97 90 top
R91  10K  [R0402L]  87.25 15.37 90 top
R92  NC/0R  [R0402L]  22.56 26.97 270 bottom
R93  NC/0R  [R0402L]  31.09 26.97 270 bottom
R94  NC/0R  [R0402L]  32.05 26.97 270 bottom
R95  NC/0R  [R0402L]  28.96 26.97 270 bottom
R96  NC/0R  [R0402L]  30.02 26.97 270 bottom
R97  NC/0R  [R0402L]  26.82 26.97 270 bottom
R98  NC/0R  [R0402L]  27.89 26.97 270 bottom
R99  NC/0R  [R0402L]  24.69 26.97 270 bottom
R100  NC/0R  [R0402L]  25.76 26.97 270 bottom
R101  NC/0R  [R0402L]  23.62 26.97 270 bottom
R102  22R  [R0402L]  11.81 23.22 90 bottom
R103  10K  [R0402L]  33.22 26.97 270 bottom
R104  82K  [R0402L]  12.67 22.38 270 top
R105  100K  [R0402L]  11.81 25.02 90 bottom
R106  2R  [R0805L]  19.66 24.23 0 bottom
R107  2R  [R0805L]  19.66 26.21 0 bottom
R108  22R  [R0402L]  39.62 32.64 0 bottom
R109  2.2K  [R0402L]  78.49 73.03 90 bottom
R110  2.2K  [R0402L]  80.77 73.03 90 bottom
R111  22R  [R0402L]  75.44 26.82 270 bottom
R112  22R  [R0402L]  74.19 26.82 270 bottom
R113  22R  [R0402L]  73.03 26.85 270 bottom
R114  22R  [R0402L]  71.88 26.8 270 bottom
R115  82K  [R0402L]  39.62 31.24 180 bottom
R116  100K  [R0402L]  39.62 34.04 180 bottom
R117  2R  [R0805L]  49.58 24.69 0 bottom
R118  2R  [R0805L]  49.58 26.82 0 bottom
R119  10K  [R0402L]  62.87 27.81 180 bottom
R120  4.7K  [R0402L]  28.55 20.27 180 top
R121  1K  [R0402L]  28.55 21.31 180 top
R122  4.7K  [R0402L]  28.5 25.76 180 top
R125  0R  [R0402L]  20.19 28.45 0 top
R126  NC/10K  [R0402L]  36.2 12.57 180 top
R127  NC/10K  [R0402L]  34.04 14.22 270 top
R128  0R  [R0402L]  34.29 12.57 180 top
R129  100K  [R0402L]  45.97 13.34 90 top
R130  0R  [R0402L]  31.39 12.93 0 top
R131  10K  [R0402L]  46.99 13.34 90 top
R132  0R  [R0402L]  28.57 63.25 180 top
R133  0R  [R0402L]  28.57 62.23 180 top
R134  0R  [R0402L]  28.57 65.41 180 top
R135  0R  [R0402L]  28.57 64.39 180 top
R136  0R  [R0402L]  28.57 69.47 180 top
R137  0R  [R0402L]  28.57 68.45 180 top
R138  0R  [R0402L]  28.57 71.5 180 top
R139  0R  [R0402L]  28.57 70.48 180 top
R140  0R  [R0402L]  28.57 67.44 180 top
R141  0R  [R0402L]  28.57 66.42 180 top
R142  0R  [R0402L]  21.34 62.36 0 top
R143  22R  [R0402L]  92.84 37.47 180 bottom
R144  22R  [R0402L]  94.87 42.04 180 bottom
R145  22R  [R0402L]  94.87 43.18 180 bottom
R146  2.2K  [R0402L]  96.77 43.18 0 bottom
R147  2.2K  [R0402L]  96.77 42.04 0 bottom
R148  10K  [R0402L]  25.91 61.42 0 bottom
R149  10K  [R0402L]  34.54 60.96 180 bottom
R150  10K  [R0402L]  34.54 57.15 180 bottom
R151  10K  [R0402L]  34.54 53.09 180 bottom
R152  NC/10K  [R0402L]  110.74 64.64 270 top
R153  22R  [R0402L]  110.74 62.74 270 top
R154  22R  [R0402L]  109.6 62.74 270 top
R155  22R  [R0402L]  115.52 62.79 270 top
R156  22R  [R0402L]  114.45 62.79 270 top
R157  NC/10K  [R0402L]  113.13 64.67 270 top
R158  22R  [R0402L]  113.13 62.79 270 top
R159  22R  [R0402L]  99.06 58.42 0 bottom
R160  15K  [R0402L]  77.47 73.03 90 bottom
R161  20K  [R0402L]  103.61 52.1 0 top
R162  15K  [R0402L]  121.92 53.34 180 top
R163  0R  [R0402L]  120.24 59.74 270 top
R164  20K  [R0402L]  119.63 53.34 0 top
R165  10K  [R0402L]  71.37 70.36 270 bottom
R166  10K  [R0402L]  119.63 54.61 180 top
R168  0R  [R0402L]  116.74 62.79 270 top
R170  NC/0R  [R0402L]  119.63 56.06 180 top
R171  NC/0R  [R0402L]  121.92 56.06 180 top
R172  0R  [R0402L]  103.63 57.91 180 top
R173  NC/10K  [R0402L]  103.63 48.26 180 top
R174  NC/0R  [R0805L]  124.82 62.94 180 top
R175  100K  [R0402L]  126.64 60.2 270 top
R176  10K  [R0402L]  103.63 56.9 0 top
R177  0R  [R0402L]  113.28 42.11 90 top
R178  10K  [R0402L]  125.86 57.78 180 top
R179  NC/0R  [R0402L]  103.78 53.34 180 top
R181  0R  [R0402L]  103.61 51.05 0 top
R182  NC/0R  [R0402L]  103.63 49.4 0 top
R183  2.2R  [R0402L]  110.44 75.54 90 bottom
R184  2.2R  [R0402L]  109.37 75.54 90 bottom
R185  2.2R  [R0402L]  108.31 75.54 90 bottom
R186  2.2R  [R0402L]  107.24 75.54 90 bottom
R187  2.2R  [R0402L]  106.17 75.54 90 bottom
R188  2.2R  [R0402L]  105.11 75.54 90 bottom
R189  2.2R  [R0402L]  104.04 75.54 90 bottom
R190  2.2R  [R0402L]  102.97 75.54 90 bottom
R191  510R  [R0402L]  101.35 77.47 270 top
R192  510R  [R0402L]  98.93 77.6 270 top
R193  100R  [R0402L]  101.6 70.87 0 bottom
R194  120R  [R0402L]  99.82 70.48 90 bottom
R195  NC/4.7K  [R0402L]  104.14 68.45 90 top
R196  4.7K  [R0402L]  103.15 68.45 90 top
R197  22R  [R0402L]  84.33 25.53 90 bottom
R198  22R  [R0402L]  85.47 25.53 90 bottom
R199  NC/4.7K  [R0402L]  104.85 70.41 180 top
R200  4.7K  [R0402L]  103.17 70.43 270 top
R201  22R  [R0402L]  78.99 24 90 bottom
R202  22R  [R0402L]  80.01 24 90 bottom
R203  4.7K  [R0402L]  100.08 77.6 90 top
R204  22R  [R0402L]  86.61 25.53 90 bottom
R205  22R  [R0402L]  82.93 25.53 90 bottom
R206  4.7K  [R0402L]  106.15 68.99 270 top
R207  4.7K  [R0402L]  110.06 66.5 270 top
R208  4.7K  [R0402L]  103.25 66.42 270 bottom
R209  NC/4.7K  [R0402L]  105.41 66.5 270 top
R210  4.7K  [R0402L]  107.14 68.99 270 top
R211  NC/4.7K  [R0402L]  106.96 66.5 270 top
R212  2.49K  [R0402L]  101.6 74.3 0 bottom
R213  4.7K  [R0402L]  108.1 68.99 270 top
R214  NC/4.7K  [R0402L]  107.92 66.5 270 top
R215  0R  [R0402L]  97.41 77.22 180 top
R216  NC/4.7K  [R0402L]  109.09 69.85 270 top
R217  4.7K  [R0402L]  108.99 66.5 270 top
R218  NC/10K  [R0402L]  111.86 72.77 270 top
R219  0R  [R0402L]  75.44 72.14 90 bottom
R220  1.8K  [R0402L]  109.42 72.26 180 top
R221  0R  [R0402L]  92.33 73.66 90 bottom
R222  NC/0R  [R0402L]  91.31 75.56 270 bottom
R223  22R  [R0402L]  105.41 65.53 270 bottom
R224  22R  [R0402L]  106.43 65.53 270 bottom
R225  22R  [R0402L]  107.44 66.04 270 bottom
R226  22R  [R0402L]  108.46 66.55 270 bottom
R227  22R  [R0402L]  100.71 65.91 180 bottom
R228  22R  [R0402L]  104.39 65.53 270 bottom
R229  0R  [R0402L]  111.51 74.68 270 bottom
R230  2.2R  [R0402L]  124.97 73.76 90 bottom
R231  2.2R  [R0402L]  123.9 73.76 90 bottom
R232  2.2R  [R0402L]  122.83 73.76 90 bottom
R233  2.2R  [R0402L]  121.77 73.76 90 bottom
R234  2.2R  [R0402L]  120.8 73.76 90 bottom
R235  2.2R  [R0402L]  119.84 73.76 90 bottom
R236  2.2R  [R0402L]  118.82 73.48 90 bottom
R237  2.2R  [R0402L]  117.83 73.48 90 bottom
R238  510R  [R0402L]  112.52 75.82 270 bottom
R239  510R  [R0402L]  138.99 95.25 0 top
R240  100R  [R0402L]  115.67 68.88 0 bottom
R241  120R  [R0402L]  114.17 68.45 270 bottom
R242  NC/4.7K  [R0402L]  116.59 67.54 0 top
R243  4.7K  [R0402L]  116.59 66.5 0 top
R244  22R  [R0402L]  99.19 48.01 270 bottom
R245  22R  [R0402L]  98.17 48.01 270 bottom
R246  NC/4.7K  [R0402L]  115.65 69.75 0 top
R247  4.7K  [R0402L]  113.03 74.42 180 bottom
R248  22R  [R0402L]  97.79 51.05 270 bottom
R249  22R  [R0402L]  97.54 52.96 270 bottom
R250  4.7K  [R0402L]  115.67 67.82 0 bottom
R251  4.7K  [R0402L]  123.8 65.07 270 top
R252  22R  [R0402L]  100.2 48.01 270 bottom
R253  22R  [R0402L]  99.06 51.56 270 bottom
R254  4.7K  [R0402L]  118.75 62.74 90 bottom
R255  NC/4.7K  [R0402L]  119.13 65.15 180 bottom
R256  4.7K  [R0402L]  120.65 64.77 90 bottom
R257  4.7K  [R0402L]  121.28 67.31 270 top
R258  NC/4.7K  [R0402L]  120.78 65.07 270 top
R259  2.49K  [R0402L]  117.2 71.32 270 top
R260  4.7K  [R0402L]  122.3 67.31 270 top
R261  NC/4.7K  [R0402L]  121.79 65.07 270 top
R262  0R  [R0402L]  95.12 68.33 270 bottom
R263  NC/4.7K  [R0402L]  123.32 67.31 270 top
R264  4.7K  [R0402L]  122.78 65.07 270 top
R265  1M  [R0805L]  140.97 90.22 180 top
R266  NC/10K  [R0402L]  124.28 71.35 270 top
R267  0R  [R0402L]  70.1 70.36 270 bottom
R268  1.8K  [R0402L]  125.12 69.88 0 bottom
R269  0R  [R0402L]  91.31 73.66 90 bottom
R270  NC/0R  [R0402L]  89.28 73.66 90 bottom
R271  22R  [R0402L]  121.67 64.77 270 bottom
R272  22R  [R0402L]  122.94 62.87 270 bottom
R273  22R  [R0402L]  122.94 64.77 270 bottom
R274  22R  [R0402L]  123.95 64.77 270 bottom
R275  22R  [R0402L]  119.76 62.74 270 bottom
R276  22R  [R0402L]  121.28 62.87 270 bottom
R277  0R  [R0402L]  125.63 73.13 270 top
R278  22R  [R0402L]  12.95 61.09 180 bottom
R282  NC/22R  [R0402L]  18.16 67.82 180 bottom
R284  NC/22R  [R0402L]  18.16 66.55 180 bottom
R286  22R  [R0402L]  17.98 58.52 270 bottom
R287  10K  [R0402L]  21.84 53.59 0 bottom
R288  22K  [R0402L]  19.35 58.52 270 bottom
R289  1.5K  [R0603L]  13.72 52.88 0 bottom
R290  NC/120R  [R1206L]  15.34 43.99 90 bottom
R291  22R  [R0402L]  16.51 49.53 0 bottom
R292  1.5K  [R0603L]  13.72 54.41 180 bottom
R293  10K  [R0402L]  20.83 53.09 270 top
R294  10K  [R0402L]  21.97 47.12 0 bottom
R295  22K  [R0402L]  17.4 51.82 0 bottom
R296  1.5K  [R0603L]  14.1 47.62 0 bottom
R297  NC/120R  [R1206L]  10.01 35.48 0 bottom
R298  1.5K  [R0603L]  14.1 49.15 180 bottom
R299  10K  [R0402L]  20.83 51.05 90 top
R300  0R  [R0402L]  12.01 45.09 0 top
R301  10K  [R0402L]  12.01 42.77 0 top
R302  2.2K  [R0402L]  22.1 44.58 0 bottom
R303  60.4R  [R0603L]  19.81 41.61 0 bottom
R304  60.4R  [R0603L]  19.81 40.08 0 bottom
R305  2.2K  [R0402L]  22.86 37.19 90 bottom
R306  10K  [R0402L]  22.25 36.42 90 top
R307  10K  [R0402L]  11.73 34.75 0 top
R308  2.2K  [R0402L]  22.86 34.29 90 bottom
R309  10K  [R0402L]  21.44 32.77 180 top
R310  60.4R  [R0603L]  19.81 37.49 0 bottom
R311  60.4R  [R0603L]  19.81 35.97 0 bottom
R312  2.2K  [R0402L]  121.67 44.45 0 top
R313  2.2K  [R0402L]  115.06 43.31 0 top
R316  22R  [R0402L]  115.06 42.29 180 top
R317  22R  [R0402L]  119.76 44.45 0 top
R318  2.2K  [R0402L]  66.04 35.18 270 bottom
R319  2.2K  [R0402L]  62.99 35.18 90 bottom
R320  22R  [R0402L]  65.02 35.18 90 bottom
R321  22R  [R0402L]  64.01 35.18 90 bottom
R322  0R  [R0402L]  67.06 35.18 270 bottom
R323  NC/10K  [R0402L]  65.41 42.29 270 bottom
R324  10K  [R0402L]  66.42 42.29 90 bottom
R325  22R  [R0402L]  111.89 34.04 270 bottom
R326  22R  [R0402L]  111.89 37.72 90 top
R327  22R  [R0402L]  113.28 37.72 90 top
R328  0R  [R0402L]  112.39 19.96 270 top
R329  22R  [R0402L]  112.9 34.04 270 bottom
R330  10K  [R0402L]  113.92 34.04 90 bottom
R331  0R  [R0402L]  113.46 19.96 270 top
R332  0R  [R0402L]  116.59 19.94 270 top
R333  0R  [R0402L]  117.6 19.94 270 top
R334  1K  [R0402L]  130.94 19.94 270 top
R335  0R  [R0402L]  120.27 37.72 90 top
R336  0R  [R0402L]  121.41 37.72 90 top
R337  10K  [R0402L]  126.36 34.29 180 bottom
R338  100K  [R0402L]  126.36 33.27 0 bottom
R339  15K  [R0402L]  110.74 37.72 90 top
R340  200K  [R0402L]  107.42 43.05 270 top
R341  37.4K  [R0402L]  109.98 42.67 0 top
R342  10K  [R0402L]  105.03 42.16 0 top
R343  22R  [R0402L]  79.88 46.86 0 bottom
R344  22R  [R0402L]  79.88 45.85 0 bottom
R345  NC/22R  [R0402L]  88.01 48.13 0 bottom
R346  4.7K  [R0402L]  92.84 40.01 0 bottom
R347  4.7K  [R0402L]  92.84 38.99 0 bottom
R348  4.7K  [R0402L]  92.84 41.02 0 bottom
R349  4.7K  [R0402L]  92.84 42.04 0 bottom
R350  4.7K  [R0402L]  92.84 43.05 0 bottom
R351  4.7K  [R0402L]  92.84 44.07 0 bottom
R352  4.7K  [R0402L]  92.84 45.09 0 bottom
R353  4.7K  [R0402L]  92.84 46.1 0 bottom
R354  NC4.7K  [R0402L]  79.88 43.69 180 bottom
R355  NC/4.7K  [R0402L]  79.88 42.67 180 bottom
R356  4.7K  [R0402L]  79.88 41.66 180 bottom
R357  4.7K  [R0402L]  77.6 41.02 180 bottom
R358  4.7K  [R0402L]  79.88 40.51 180 bottom
R359  4.7K  [R0402L]  77.6 40.01 180 bottom
R360  4.7K  [R0402L]  77.6 38.99 180 bottom
R361  4.7K  [R0402L]  79.88 39.24 180 bottom
R362  4.7K  [R0402L]  94.87 46.99 180 bottom
R363  4.7K  [R0402L]  94.87 48.26 180 bottom
R364  NC/4.7K  [R0402L]  78.11 44.2 90 bottom
R365  NC/0R  [R0402L]  92.84 48.13 0 bottom
R366  0R  [R0402L]  79.88 44.83 180 bottom
R367  0R  [R0402L]  11.81 37.77 0 top
R368  0R  [R0805L]  20.5 82.93 0 top
R369  0R  [R0805L]  20.5 84.91 0 top
R370  0R  [R0402L]  21.34 67.82 180 top
R371  0R  [R0402L]  21.34 65.41 180 top
R372  NC/0R  [R0402L]  18.03 57.78 0 top
R373  NC/0R  [R0402L]  21.34 61.09 180 top
R374  NC/100K  [R0402L]  61.34 12.7 270 top
R375  NC/100K  [R0402L]  62.48 12.7 90 top
R376  22R  [R0402L]  117.47 37.97 90 top
R377  NC/0R  [R0402L]  28.57 60.71 180 top
R378  NC/10K  [R0402L]  83.82 17.27 0 bottom
R379  0R  [R0402L]  85.72 17.27 0 bottom
R380  NC/10K  [R0402L]  86.23 19.05 270 bottom
R381  6.8K  [R0402L]  136.65 58.17 180 top
R382  510K  [R0402L]  134.11 58.17 0 top
R383  22R  [R0402L]  12.98 57.53 180 bottom
R384  NC/22R  [R0402L]  19 68.99 180 bottom
R385  NC/22R  [R0402L]  18.19 65.35 180 bottom
R386  100K  [R0402L]  26.16 63.45 270 bottom
R387  113K  [R0402L]  28.6 57.63 180 top
R388  100K  [R0402L]  28.6 58.55 0 top
R389  80.6K  [R0402L]  26.16 65.1 270 bottom
R390  100K  [R0402L]  26.14 55.37 90 bottom
R391  40.2K  [R0402L]  25.25 55.37 270 bottom
SIM1  SIM  [SIM-91288-021]  112.32 28.65 90 bottom
SW1  T-switch  [PB-SIDE-P-4_5X4_5]  142.19 99.21 270 top
TP1  -  [TP100]  68.96 42.29 180 bottom
TP2  -  [TP100]  4.95 75.69 180 bottom
TP3  -  [TP100]  3.05 75.69 180 bottom
TP4  -  [TP100]  4.95 63.12 180 bottom
TP5  -  [TP100]  3.17 64.01 180 bottom
TP6  -  [TP100]  3.17 60.33 180 bottom
TP7  -  [TP100]  3.17 53.59 180 bottom
TP8  -  [TP100]  3.17 47.37 180 bottom
TP9  -  [TP100]  3.17 40.77 180 bottom
TP10  -  [TP100]  3.02 29.87 180 bottom
TP11  -  [TP100]  3.07 37.31 180 bottom
TP12  -  [TP100]  5.08 17.14 180 bottom
TP13  -  [TP100]  3.17 23.37 180 bottom
TP14  -  [TP100]  3.17 10.92 180 bottom
TP15  -  [TP100]  3.17 17.14 180 bottom
TP16  -  [TP100]  12.32 72.26 180 bottom
TP17  -  [TP100]  6.22 53.59 180 bottom
TP18  -  [TP100]  6.22 40.77 180 bottom
TP19  -  [TP100]  3.17 25.53 180 bottom
TP20  -  [TP100]  7.62 17.14 180 bottom
TP21  -  [TP100]  7.75 10.92 180 bottom
TP22  -  [TP100]  6.35 61.72 180 bottom
TP23  -  [TP100]  6.35 37.21 180 bottom
TP24  -  [TP100]  105.66 3.3 180 bottom
TP25  -  [TP100]  105.79 5.33 180 bottom
TP26  -  [TP100]  107.82 7.37 180 bottom
TP27  -  [TP100]  105.79 7.37 180 bottom
U1  ETA1654  [SOT563]  64.26 82.68 0 top
U2  TLV62569DBVR  [SOT23-5]  31.24 47.88 180 bottom
U4  SY6280AAC  [SOT23-5]  65 82.75 270 bottom
U5  SY6280AAC  [SOT23-5]  49.45 82.25 270 top
U6  SY6280AAC  [SOT23-5]  71.02 82.04 270 bottom
U7  SY6280AAC  [SOT23-5]  79.48 81.92 0 top
U8  FE2.1  [FE2_1-LQFP48]  81.38 61.87 0 bottom
U9  SY6280AAC  [SOT23-5]  87.53 81.53 180 bottom
U10  SY6280AAC  [SOT23-5]  93.88 80.31 0 top
U11  SY6280AAC  [SOT23-5]  135.38 45.85 180 top
U12  SY6280AAC  [SOT23-5]  135.51 65.66 180 top
U13  NS4205  [NS4205-SOP16]  104.09 13.72 90 bottom
U14  NC/74LVC1G125GW,125  [SOT353]  71.53 13.87 270 top
U15  SY7201ABC  [SOT23-6]  14 24.89 0 top
U16  SY7201ABC  [SOT23-6]  42.37 32.61 90 bottom
U17  GM8775C  [QFN50P700X700X100-49AN]  22.56 22.56 180 top
U18  NC/74LVC1G125GW,125  [SOT353]  31.5 12.9 0 top
U19  ME6211C18M5G-N  [SOT23-5]  31.24 62.1 180 bottom
U20  ME6211C15M5G-N  [SOT23-5]  31.24 58.42 180 bottom
U21  ME6211C28M5G-N  [SOT23-5]  31.24 54.74 180 bottom
U23  AP6256  MODULE  [MD44_AP6XXX]  111.4 54.25 180 top
U24  RTL8211F-CG  [RTL8211F-CG-QFN40]  106.83 70.87 270 bottom
U25  RTL8211F-CG  [RTL8211F-CG-QFN40]  120.85 69.19 270 bottom
U26  SP3232EEY-L/TR  [SP3232EEY-TSSOP-16]  16.15 67.97 0 top
U27  SP3232EEY-L/TR  [SP3232EEY-TSSOP-16]  16.15 61.26 0 top
U28  MC74VHC1G04DFT2G  [SOT353]  19.35 55.47 270 bottom
U29  SP485EEN-L/TR  [SOP8-P127-390X490]  16.61 53.64 180 top
U30  MC74VHC1G04DFT2G  [SOT353]  20.7 49.02 0 bottom
U31  SP485EEN-L/TR  [SOP8-P127-390X490]  16.61 48.01 180 top
U32  TJA1044  [SOP8-P127-390X490]  16.61 42.21 180 top
U33  TJA1044  [SOP8-P127-390X490]  16.61 36.58 180 top
U34  HYM8563TS  [PCF85063ATT-TSSOP8]  119.66 42.32 180 top
U35  MPU6500  [MPU6500-QFN-24]  66.01 38.81 0 bottom
U36  NC/PCIE_M2_NGFF-B-KEY  [PCIE_M2_NGFF-B-KEY]  107.44 28.04 0 top
U37  TLV62569DBVR  [SOT23-5]  108.31 40.64 0 top
U38  PCA9548PW  [PCA9539PW-TSSOP24]  86.44 43.21 180 bottom
U39  ETA1654  [SOT563]  26.29 50.16 90 top
U40  SY6280AAC  [SOT23-5]  135.38 55.75 180 top
XT1  12MHz  [XTAL_32X25_4P]  83.97 73.3 270 bottom
XT3  NC/37.4MHz  [XTAL_32X25_4P]  120.42 62.32 90 top
XT4  25MHz  [XTAL_32X25_4P]  98.55 73.41 180 bottom
XT5  25MHz  [XTAL_32X25_4P]  114.3 71.55 180 bottom
XT6  32.768KHz  [XTAL_32X15_2P]  125.68 41.71 90 top

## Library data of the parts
C2 C7 C8 C12 C14 C16 C18 C19 C23 C24 C34 C36 C37 C40 C42 C46 C47 C50 C51 C60 C64 C65 C68-C76 C80-C91 C94-C106 C113 C114 C121 C122 C126 C129-C131 C133-C135 C145 C146 C149 C152-C158 C161-C165 C167-C197 C199-C205 C207-C245 C248 C249 C251 C252 C254 C259-C262 C264 C265 C268-C273 C278 C482-C485 C491-C494 C496 C497 = C-0402
C3 C6 C9-C11 C22 C25-C27 C48 C110 C112 C138 C140 C142 C486 C488 = C-0805
C4 = C-AL-SMD
C17 C20 C21 C30-C33 C35 C38 C41 C43 C45 C52-C59 C61-C63 C66 C67 C77-C79 C92 C93 C107 C108 C111 C115-C120 C123-C125 C127 C128 C132 C139 C141 C143 C144 C147 C148 C150 C151 C166 C246 C247 C253 C255-C258 C263 C266 C267 C274-C277 C489 C490 = C-0603
C206 = C-1206
D1 D10 D49 D51 D56 D60 D82-D84 D86 D88 D90 D92 D93 D107 = DI-XI-S
